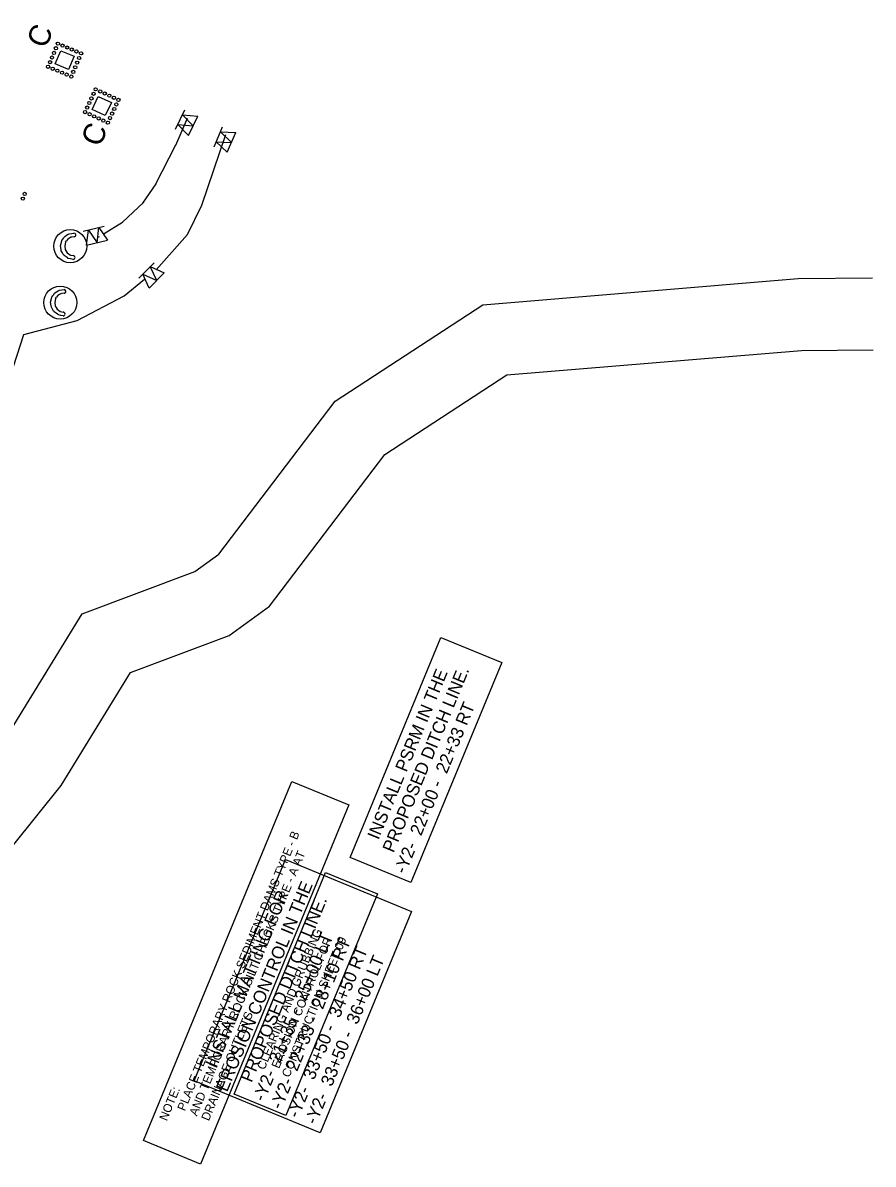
# Model space of a CAD drawing. Extents: x 2470000 to 2520000, y 340000 to 380000.
# Drawn here: x 2483235 to 2483827, y 367994 to 368789 of the extents above; entities that cross this region are included whole.
import ezdxf

# ---------------------------------------------------------------- set-up
doc = ezdxf.new("R2010")
doc.units = 0
for name, color, linetype in [('Coir Fiber Wattle with PAM Final CELL', 7, 'Continuous'), ('Construction Sheet Number Note CG CELL', 7, 'Continuous'), ('Matting in Proposed Ditchline Note Final CELL', 7, 'Continuous'), ('Prop Guardrail', 7, 'Continuous'), ('Prop Guardrail Anchor Unit CELL', 7, 'Continuous'), ('Prop Structure Anchor Unit CELL', 7, 'Continuous'), ('PSRM in Proposed Ditchline Note Final CELL', 7, 'Continuous'), ('Scratch_Level_4', 7, 'Continuous'), ('Scratch_Level_5', 7, 'Continuous'), ('Sediment Dams and Silt Check Note CG CELL', 7, 'Continuous'), ('Sheet Data Field CELL', 7, 'Continuous'), ('Special Sediment Control Fence Section Both CELL', 7, 'Continuous'), ('Temporary Silt Fence CG', 7, 'Continuous')]:
    doc.layers.add(name, color=color, linetype=linetype)

# ---------------------------------------------------------------- blocks, each defined once
blk = doc.blocks.new('C3')
at = {"layer": 'Prop Guardrail'}
blk.add_text('C', height=0.3, dxfattribs=at).set_placement((-0.161, -0.136))
blk = doc.blocks.new('C2')
at = {"layer": 'Prop Guardrail Anchor Unit CELL'}
blk.add_text('C', height=0.3, dxfattribs=at).set_placement((-0.161, -0.136))
blk = doc.blocks.new('CGNT2')
at = {"layer": 'Sediment Dams and Silt Check Note CG CELL'}
blk.add_lwpolyline([(-2.704, 0.431), (2.704, 0.43125), (2.704, -0.43), (-2.704, -0.43)], close=True, dxfattribs=at)
for s, p in [('NOTE:', (-2.335, 0.231)), ('     PLACE TEMPORARY ROCK SEDIMENT DAMS TYPE - B', (-2.335, 0.05125)), ('     AND TEMPORARY ROCK SILT CHECKS TYPE - A AT', (-2.335, -0.129)), ('     DRAINAGE OUTLETS.', (-2.335, -0.309))]:
    blk.add_text(s, height=0.12, dxfattribs=at).set_placement(p)

msp = doc.modelspace()

# ---------------------------------------------------------------- linework, layer by layer
at = {"layer": 'Coir Fiber Wattle with PAM Final CELL'}
for p, q in [((2483266.57, 368637.76), (2483265.94, 368636.84)), ((2483266.57, 368637.76), (2483266.7, 368637.96)), ((2483267.94, 368638.71), (2483266.7, 368637.96)), ((2483268.88, 368639.28), (2483267.94, 368638.71)), ((2483269.66, 368639.4), (2483268.88, 368639.28)), ((2483271.2, 368639.61), (2483269.66, 368639.4)), ((2483265.28, 368635.85), (2483264.72, 368633.28)), ((2483264.72, 368633.27), (2483264.72, 368633.28)), ((2483264.72, 368633.27), (2483265.05, 368630.75)), ((2483265.05, 368630.75), (2483265.65, 368629.71)), ((2483265.28, 368635.85), (2483265.94, 368636.84)), ((2483265.65, 368629.71), (2483266.36, 368628.45)), ((2483266.36, 368628.45), (2483267.21, 368627.86)), ((2483267.21, 368627.86), (2483268.42, 368627.01)), ((2483268.74, 368626.94), (2483268.42, 368627.01)), ((2483268.74, 368626.94), (2483270.56, 368626.52)), ((2483259.62, 368598.48), (2483259, 368597.56)), ((2483259.62, 368598.48), (2483259.76, 368598.67)), ((2483261, 368599.43), (2483259.76, 368598.67)), ((2483261.94, 368600), (2483261, 368599.43)), ((2483262.72, 368600.11), (2483261.94, 368600)), ((2483264.26, 368600.33), (2483262.72, 368600.11)), ((2483258.34, 368596.57), (2483257.78, 368594)), ((2483257.78, 368593.99), (2483257.78, 368594)), ((2483257.78, 368593.99), (2483258.11, 368591.47)), ((2483258.11, 368591.47), (2483258.71, 368590.42)), ((2483258.34, 368596.57), (2483259, 368597.56)), ((2483258.71, 368590.42), (2483259.42, 368589.16)), ((2483259.42, 368589.16), (2483260.27, 368588.58)), ((2483260.27, 368588.58), (2483261.48, 368587.73)), ((2483261.8, 368587.65), (2483261.48, 368587.73)), ((2483261.8, 368587.65), (2483263.62, 368587.24))]:
    msp.add_line(p, q, dxfattribs=at)
for points in [[(2483270.46, 368623.93), (2483268.94, 368624.25), (2483267.16, 368624.63), (2483266.47, 368625.11), (2483265.64, 368625.69), (2483264.17, 368626.71), (2483264.15, 368626.74), (2483263.92, 368627.12), (2483263.88, 368627.18), (2483263.39, 368628), (2483263.04, 368628.58), (2483262.29, 368629.83), (2483262.13, 368630.86), (2483261.75, 368633.38), (2483261.75, 368633.39), (2483262.34, 368635.96), (2483262.57, 368636.97), (2483263.23, 368637.89), (2483263.37, 368638.08), (2483263.93, 368638.86), (2483264.36, 368639.45), (2483264.46, 368639.59), (2483264.67, 368639.89), (2483264.68, 368639.9), (2483265.98, 368640.67), (2483267.13, 368641.35), (2483267.83, 368641.76), (2483269.57, 368642.03), (2483271.1, 368642.27)], [(2483263.52, 368584.64), (2483262, 368584.97), (2483260.22, 368585.35), (2483259.53, 368585.82), (2483258.7, 368586.4), (2483257.23, 368587.42), (2483257.2, 368587.46), (2483256.98, 368587.84), (2483256.94, 368587.9), (2483256.44, 368588.72), (2483256.1, 368589.29), (2483255.35, 368590.55), (2483255.19, 368591.58), (2483254.81, 368594.1), (2483254.81, 368594.11), (2483255.4, 368596.68), (2483255.63, 368597.68), (2483256.29, 368598.6), (2483256.43, 368598.8), (2483256.99, 368599.58), (2483257.42, 368600.17), (2483257.52, 368600.31), (2483257.73, 368600.61), (2483257.74, 368600.61), (2483259.04, 368601.38), (2483260.19, 368602.07), (2483260.89, 368602.48), (2483262.62, 368602.75), (2483264.15, 368602.99)]]:
    msp.add_lwpolyline(points, dxfattribs=at)
for centre in [(2483268.52, 368633.11), (2483261.58, 368593.83)]:
    msp.add_circle(centre, 11.5, dxfattribs=at)
for centre, radius, start in [((2483271.05, 368640.94), 1.33, 276.74001), ((2483270.51, 368625.23), 1.3, 267.85264), ((2483264.1, 368601.65), 1.33, 276.74001), ((2483263.57, 368585.94), 1.3, 267.85264)]:
    msp.add_arc(centre, radius, start, 87.85264, dxfattribs=at)
at = {"layer": 'Construction Sheet Number Note CG CELL'}
msp.add_lwpolyline([(2483382.46, 368043.04), (2483446.17, 368197.3), (2483482.22, 368182.41), (2483418.52, 368028.15)], close=True, dxfattribs=at)
at = {"layer": 'Matting in Proposed Ditchline Note Final CELL'}
msp.add_lwpolyline([(2483354.74, 368052.28), (2483418.31, 368206.24), (2483505.96, 368170.05), (2483442.39, 368016.09)], close=True, dxfattribs=at)
at = {"layer": 'Prop Structure Anchor Unit CELL'}
msp.add_lwpolyline([(2483283.81, 368728.22), (2483288.02, 368737.29), (2483297.09, 368733.07), (2483292.86, 368724.01)], close=True, dxfattribs=at)
for centre in [(2483286.18, 368742.27), (2483289.36, 368740.79), (2483281.76, 368732.75), (2483283.23, 368735.92), (2483284.71, 368739.1), (2483292.53, 368739.32), (2483295.71, 368737.84), (2483298.88, 368736.37), (2483302.05, 368734.89), (2483278.81, 368726.4), (2483280.28, 368729.57), (2483281.98, 368724.93), (2483297.63, 368725.37), (2483299.1, 368728.55), (2483300.58, 368731.72), (2483285.15, 368723.45), (2483288.33, 368721.97), (2483291.5, 368720.5), (2483294.68, 368719.02), (2483296.15, 368722.2)]:
    msp.add_circle(centre, 1.12, dxfattribs=at)
at = {"layer": 'PSRM in Proposed Ditchline Note Final CELL'}
msp.add_lwpolyline([(2483463.23, 368207.74), (2483526.46, 368360.82), (2483568.82, 368343.32), (2483505.59, 368190.24)], close=True, dxfattribs=at)
at = {"layer": 'Scratch_Level_4'}
for points in [[(2483085.04, 368065.06), (2483127.66, 368135.84), (2483168.66, 368221.22), (2483221.15, 368286.55), (2483276.76, 368377.26), (2483355.23, 368406.68), (2483371.87, 368418.81), (2483452.82, 368525.26), (2483555.67, 368592.37), (2483775.05, 368610.58), (2483826.84, 368610.97)], [(2483098.83, 368010.77), (2483127.36, 368038.42), (2483171.71, 368112.07), (2483211.24, 368194.39), (2483262.11, 368257.71), (2483310.4, 368336.47), (2483379.17, 368362.25), (2483407.24, 368382.72), (2483487.39, 368488.11), (2483572.4, 368543.59), (2483777.32, 368560.59), (2483827.22, 368560.98)]]:
    msp.add_lwpolyline(points, dxfattribs=at)
at = {"layer": 'Scratch_Level_5'}
msp.add_lwpolyline([(2483258.02, 368759.92), (2483261.91, 368769.14), (2483271.12, 368765.25), (2483267.23, 368756.04)], close=True, dxfattribs=at)
for centre in [(2483259.89, 368774.05), (2483263.11, 368772.69), (2483255.81, 368764.38), (2483257.17, 368767.6), (2483258.53, 368770.83), (2483266.34, 368771.33), (2483269.57, 368769.97), (2483272.79, 368768.61), (2483274.66, 368764.03), (2483276.02, 368767.25), (2483253.09, 368757.93), (2483254.45, 368761.15), (2483256.32, 368756.57), (2483271.94, 368757.58), (2483273.3, 368760.8), (2483259.54, 368755.21), (2483262.77, 368753.85), (2483265.99, 368752.49), (2483269.22, 368751.13), (2483270.58, 368754.35), (2483236.75, 368669.47), (2483235.5, 368666.2)]:
    msp.add_circle(centre, 1.12, dxfattribs=at)
at = {"layer": 'Sheet Data Field CELL'}
for p, q in [((2483360.16, 368661.75), (2483376.66, 368710.87)), ((2483327.89, 368675.95), (2483342.07, 368703.6)), ((2483319.08, 368663), (2483328.19, 368676.47)), ((2483350.11, 368641.23), (2483360.16, 368661.75))]:
    msp.add_line(p, q, dxfattribs=at)
for points in [[(2483341.94, 368703.32), (2483350.12, 368722.1)], [(2483292.02, 368641.84), (2483304.96, 368649.81), (2483319.79, 368663.83)], [(2483288.25, 368639.51), (2483288.82, 368639.87)], [(2483328.35, 368616.65), (2483350.11, 368641.23)]]:
    msp.add_lwpolyline(points, dxfattribs=at)
at = {"layer": 'Special Sediment Control Fence Section Both CELL'}
for p, q in [((2483341.73, 368714.48), (2483348.28, 368727.98)), ((2483350.73, 368710.12), (2483357.28, 368723.62)), ((2483368.55, 368702.34), (2483374.44, 368716.13)), ((2483377.75, 368698.41), (2483383.63, 368712.21)), ((2483277.55, 368643.48), (2483292.14, 368646.93)), ((2483279.85, 368633.75), (2483294.45, 368637.2)), ((2483316.25, 368610.87), (2483326.81, 368621.53)), ((2483323.36, 368603.83), (2483333.91, 368614.49))]:
    msp.add_line(p, q, dxfattribs=at)
for points in [[(2483350.73, 368710.12), (2483343.37, 368717.85), (2483354, 368716.87)], [(2483354, 368716.87), (2483346.64, 368724.6), (2483357.28, 368723.62)], [(2483380.69, 368705.31), (2483372.97, 368712.69), (2483383.63, 368712.21)], [(2483377.75, 368698.41), (2483370.02, 368705.79), (2483380.69, 368705.31)], [(2483287.15, 368635.47), (2483288.49, 368646.07), (2483294.45, 368637.2)], [(2483279.85, 368633.75), (2483281.2, 368644.34), (2483287.15, 368635.47)], [(2483328.64, 368609.16), (2483324.17, 368618.86), (2483333.91, 368614.49)], [(2483323.36, 368603.83), (2483318.89, 368613.53), (2483328.64, 368609.16)]]:
    msp.add_lwpolyline(points, dxfattribs=at)
at = {"layer": 'Temporary Silt Fence CG'}
msp.add_lwpolyline([(2483204.9, 368475.35), (2483236.12, 368571.69), (2483273.41, 368581.33), (2483305.92, 368598.47), (2483320.28, 368610.11)], dxfattribs=at)

# ---------------------------------------------------------------- block references
at = {"layer": 'Prop Guardrail Anchor Unit CELL', "xscale": 50, "yscale": 50, "rotation": 68.05623472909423}
msp.add_blockref('C2', (2483286.1, 368711.52), dxfattribs=at)
at = {"layer": 'Scratch_Level_5', "xscale": 50, "yscale": 49.99999999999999, "rotation": 67.56305879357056}
msp.add_blockref('C3', (2483248.27, 368780.06), dxfattribs=at)
at = {"layer": 'Sediment Dams and Silt Check Note CG CELL', "xscale": 50.00000000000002, "yscale": 50.000000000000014, "rotation": 67.56305879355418}
msp.add_blockref('CGNT2', (2483390.94, 368127.5), dxfattribs=at)

# ---------------------------------------------------------------- texts
at = {"layer": 'Construction Sheet Number Note CG CELL'}
for s, p in [('CLEARING AND GRUBBING', (2483403.66, 368059.52)), ('EROSION CONTROL FOR', (2483413.79, 368060.45)), ('CONSTRUCTION SHEET 09', (2483420.95, 368054.23))]:
    msp.add_text(s, height=6, rotation=67.56306, dxfattribs=at).set_placement(p)
at = {"layer": 'Matting in Proposed Ditchline Note Final CELL'}
for s, p in [('EROSION CONTROL IN THE', (2483377.68, 368044.07)), ('INSTALL MATTING FOR ', (2483370.3, 368060.73)), ('PROPOSED DITCH LINE.', (2483394.66, 368050.66)), ('-Y2-  21+35 -  25+00 LT', (2483403.41, 368037.35)), ('-Y2-  22+33 -  28+10 RT', (2483415.39, 368031.84)), ('-Y2-  33+50 -  34+50 RT', (2483427.17, 368025.84)), ('-Y2-  33+50 -  36+00 LT', (2483439.55, 368021.29))]:
    msp.add_text(s, height=8.7846, rotation=67.56306, dxfattribs=at).set_placement(p)
at = {"layer": 'PSRM in Proposed Ditchline Note Final CELL'}
for s, p in [('INSTALL PSRM IN THE', (2483482.99, 368219.56)), ('PROPOSED DITCH LINE.', (2483493.52, 368210.52)), ('-Y2-  22+00 -  22+33 RT', (2483501.68, 368195.75))]:
    msp.add_text(s, height=8.7846, rotation=67.5559, dxfattribs=at).set_placement(p)

doc.saveas('drawing.dxf')
